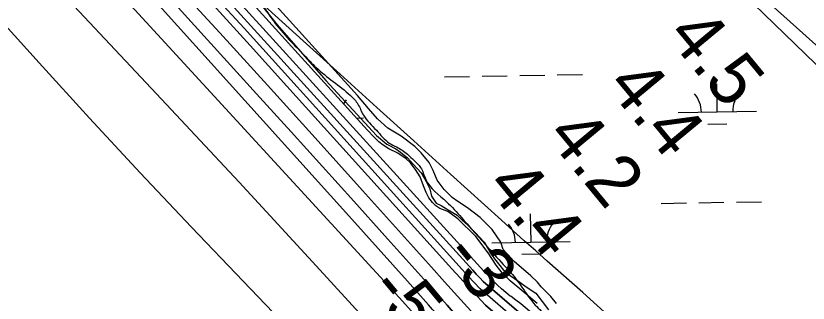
# Model space of a CAD drawing. Extents: x 3887375 to 3925618, y 296674 to 322633.
# Drawn here: x 3897913 to 3898925, y 310205 to 310572 of the extents above; entities that cross this region are included whole.
import ezdxf

# ---------------------------------------------------------------- set-up
doc = ezdxf.new("R2010")
doc.units = 0
for name, color, linetype in [('V-RIVR-EDGE', 7, 'Continuous'), ('V-RIVR-JETY', 7, 'Continuous'), ('V-RIVR-RANG', 7, 'Continuous'), ('V-TOPO-DPTH', 7, 'Continuous'), ('V-TOPO-MAJR', 7, 'Continuous'), ('V-TOPO-MINR', 7, 'Continuous'), ('V-TOPO-SHOR', 7, 'Continuous'), ('V-TOPO-WATR', 7, 'Continuous'), ('V-WETL-SWMP', 7, 'Continuous')]:
    doc.layers.add(name, color=color, linetype=linetype)

msp = doc.modelspace()

# ---------------------------------------------------------------- linework, layer by layer
at = {"layer": 'V-RIVR-EDGE'}
for points in [[(3896115.8, 312736.3), (3896123.6, 312723.7), (3896129.9, 312714.4), (3896135.6, 312703.7), (3896139.5, 312690.4), (3896139.8, 312681.4), (3896138.2, 312674.8), (3896136.8, 312674.1), (3896128.5, 312683.1), (3896119.6, 312696.5), (3896111.3, 312706.8), (3896107.3, 312707.8), (3896105, 312706.5), (3896104.3, 312701.1), (3896107.9, 312688.8), (3896111.2, 312681.2), (3896123.5, 312667.2), (3896140.7, 312647.2), (3896161, 312617.2), (3896188.5, 312584.9), (3896210, 312563.2), (3896237.6, 312538.5), (3896253.5, 312524.9), (3896271.4, 312512.5), (3896287.7, 312501.8), (3896299, 312494.8), (3896307, 312486.8), (3896325.8, 312456.2), (3896335.8, 312438.5), (3896350.7, 312424.2), (3896373.6, 312404.5), (3896404.8, 312381.8), (3896442, 312359.5), (3896468.9, 312343.4), (3896491.1, 312332.4), (3896500.1, 312327.1), (3896508.4, 312318.7), (3896515.3, 312306.4), (3896528.3, 312284.4), (3896534.9, 312271.8), (3896552.8, 312258.8), (3896583, 312239.7), (3896613.6, 312220), (3896639.8, 312198.7), (3896665.3, 312175.7), (3896698.5, 312153), (3896718.4, 312139), (3896747, 312114.6), (3896768.2, 312094.3), (3896793.7, 312068.3), (3896812.7, 312048.3), (3896828.9, 312030), (3896844.5, 312006.3), (3896867.4, 311982.3), (3896895.9, 311956), (3896949, 311910), (3896976.5, 311885.6), (3896985.2, 311878.6), (3896997.8, 311872.9), (3897005.4, 311870.2), (3897020, 311862.9), (3897041.6, 311845.9), (3897061.2, 311830.9), (3897070.1, 311823.9), (3897078.8, 311813.9), (3897087.7, 311797.5), (3897092.3, 311785.6), (3897097, 311776.9), (3897111.2, 311756.3), (3897119.5, 311747.3), (3897129.5, 311738.6), (3897149.4, 311722.6), (3897170.9, 311704.6), (3897186.2, 311690.6), (3897201.8, 311670.2), (3897228.6, 311633.3), (3897264.7, 311581.6), (3897280, 311565), (3897305.2, 311540), (3897328.4, 311515.6), (3897360.9, 311485.9), (3897388.8, 311458.3), (3897419.3, 311434.3), (3897433.9, 311420.3), (3897454.5, 311394.6), (3897475, 311368.3), (3897490.6, 311354.6), (3897505.6, 311336.6), (3897515.8, 311319.6), (3897527.8, 311305.3), (3897546.7, 311288.3), (3897564.6, 311280.6), (3897578.2, 311271.3), (3897592.8, 311257.9), (3897613.1, 311238.6), (3897630.3, 311218.9), (3897644.6, 311200.6), (3897648.9, 311196.6), (3897654.9, 311195.9), (3897664.8, 311187.9), (3897681.4, 311173.9), (3897696, 311156.2), (3897728.2, 311123.2), (3897747.7, 311099.3), (3897753.7, 311088.3), (3897756.7, 311085.6), (3897762.6, 311082.9), (3897779.6, 311067.6), (3897798.5, 311046.9), (3897815.4, 311028.6), (3897832, 311014.6), (3897852.2, 310999.9), (3897867.8, 310985.6), (3897880.8, 310970.2), (3897894, 310949.2), (3897907.6, 310928.6), (3897922.2, 310908.3), (3897948, 310879.6), (3897967.3, 310856.6), (3897987.8, 310835.3), (3898011.7, 310813.3), (3898048.6, 310785.3), (3898064.5, 310774.2), (3898081.4, 310759.2), (3898099.7, 310738.9), (3898112.9, 310724.6), (3898123.2, 310708.6), (3898130.8, 310696.3), (3898136.8, 310688.9), (3898147.4, 310677.3), (3898160, 310664.3), (3898168.9, 310655.3), (3898196.5, 310623.6), (3898206.1, 310609.3), (3898214, 310600.6), (3898230.3, 310582), (3898242.2, 310565.3), (3898262.4, 310541.3), (3898281.7, 310521.3), (3898296.6, 310506), (3898340.4, 310470.3), (3898350, 310459.3), (3898357, 310445.3), (3898373.6, 310426), (3898390.1, 310409.6), (3898399.4, 310404.6), (3898413.4, 310395.3), (3898421.7, 310387.3), (3898430, 310378.6), (3898436.6, 310363.3), (3898463.4, 310334.6), (3898482.3, 310314.6), (3898496.6, 310298.3), (3898513.2, 310279.7), (3898535.7, 310254.7), (3898547.3, 310242), (3898560.3, 310224.7), (3898576.5, 310203), (3898592.1, 310187.7), (3898611.3, 310166), (3898633.5, 310138.7), (3898638.2, 310134.4), (3898642.5, 310133), (3898652.1, 310127.7), (3898657.8, 310123.7), (3898665.4, 310115.7), (3898676.7, 310101.7), (3898686, 310090.7), (3898692.6, 310085.3), (3898699.2, 310080.3), (3898707.9, 310070), (3898714.5, 310056.4), (3898718.4, 310043.7), (3898720.4, 310041), (3898727.4, 310036.4), (3898760.3, 310015), (3898774.2, 310006), (3898785.5, 309994.3), (3898801.4, 309973.3), (3898808.7, 309959.4), (3898822.6, 309942.4), (3898837.9, 309924.7), (3898844.8, 309916.4), (3898858.7, 309899), (3898871.4, 309885.4), (3898894.5, 309850.4), (3898899.9, 309846.7), (3898908.5, 309840.7), (3898917.1, 309838), (3898920.4, 309835.7), (3898928.1, 309822.7), (3898935.4, 309812.7), (3898943.6, 309802.7), (3898951.9, 309787.7), (3898962.9, 309772.4), (3898972.5, 309757.4), (3898979.1, 309752.4), (3898987.1, 309749.1), (3898990.7, 309745.1), (3899002, 309727.8), (3899013.3, 309715.4), (3899031.2, 309696.4), (3899044.8, 309680.1), (3899055.7, 309665.5), (3899065, 309653.8), (3899074.6, 309640.1), (3899085.5, 309630.8), (3899093.8, 309628.1), (3899099.2, 309628.1), (3899103.2, 309626.1), (3899108.1, 309616.1), (3899114.7, 309606.4), (3899123.7, 309591.1), (3899128.3, 309582.8), (3899128.3, 309580.5), (3899127.6, 309569.2), (3899127.9, 309565.8), (3899132.9, 309561.5), (3899159.8, 309529.2), (3899191, 309497.2), (3899204.9, 309480.5), (3899212.2, 309470.2), (3899224.8, 309457.2), (3899244.7, 309437.5), (3899252.6, 309429.9), (3899261.9, 309422.9), (3899272.6, 309415.8), (3899279.5, 309406.5), (3899287.5, 309396.2), (3899300.1, 309376.5), (3899311.3, 309362.5), (3899327.9, 309343.2), (3899342.2, 309325.6), (3899360.1, 309304.6), (3899377.3, 309282.9), (3899414.5, 309240.6), (3899433.4, 309219.6), (3899447.3, 309203.9), (3899464.5, 309184.9), (3899479.1, 309166.9), (3899493.4, 309149.9)], [(3894498, 310522.4), (3894530, 310496.1), (3894553.8, 310474.7), (3894579.9, 310451.3), (3894614.8, 310419.2), (3894633.2, 310400.7), (3894662.8, 310372.4), (3894685.1, 310353.4), (3894692.4, 310347.1), (3894709.8, 310328.1), (3894746.6, 310285.3), (3894785.8, 310252.2), (3894809.6, 310225.9), (3894830.4, 310205.4), (3894852.7, 310189.9), (3894866.7, 310171.8), (3894915.2, 310120.3), (3894950.1, 310083.7), (3894971.4, 310062.8), (3894999, 310039.4), (3895025.2, 310017), (3895052.8, 309992.7), (3895093, 309952.3), (3895110.9, 309932.8), (3895141.4, 309903.1), (3895188.9, 309855.9), (3895222.8, 309821.3), (3895255.8, 309784.3), (3895319.2, 309722.5), (3895350.7, 309688.4), (3895358.4, 309676.3), (3895364.7, 309669.4), (3895374.9, 309663.1), (3895389, 309650.4), (3895410.8, 309628.1), (3895448.5, 309583.3), (3895480.5, 309554.1), (3895503.8, 309527.8), (3895533.8, 309499.5), (3895577.4, 309454.8), (3895606.9, 309425.5), (3895653.5, 309378.8), (3895685.9, 309349.1), (3895719.8, 309314.5), (3895749.4, 309285.8), (3895790.6, 309242.5), (3895837.1, 309195.8), (3895863.7, 309164.1), (3895900, 309127.6), (3895944.1, 309081.4), (3895955.7, 309070.7), (3895974.6, 309054.6), (3896002.3, 309033.1), (3896032.8, 309003.9), (3896062.8, 308972.3), (3896082.7, 308950.4), (3896119.5, 308911.9), (3896139.3, 308892.5), (3896152, 308889.5), (3896163.1, 308883.7), (3896167.9, 308873.9), (3896170.3, 308862.3), (3896184.4, 308844.3), (3896211, 308816), (3896224.1, 308810.2), (3896236.7, 308802.4), (3896249.8, 308786.8), (3896255.6, 308776.6), (3896270.6, 308766.4), (3896280.3, 308753.2), (3896295.8, 308737.2), (3896375.3, 308661.2), (3896425.2, 308610.1), (3896464.4, 308570.6), (3896519.6, 308515.6), (3896548.7, 308483), (3896563.2, 308467.5), (3896597.6, 308430.9), (3896635.9, 308396.4), (3896666.4, 308365.7), (3896681.4, 308349.6), (3896712.4, 308320.4), (3896746.3, 308287.3), (3896777.4, 308260), (3896801.6, 308235.7), (3896820.5, 308215.3), (3896842.8, 308195.3), (3896851.5, 308181.2), (3896882.5, 308148.6), (3896918.8, 308116.4), (3896962.9, 308074.6), (3896997.8, 308033.2), (3897029.2, 307998.6), (3897042.3, 307985), (3897083.5, 307945.6), (3897107.2, 307918.3), (3897123.2, 307898.8), (3897130, 307898.8), (3897142.1, 307893), (3897146, 307882.3), (3897149.9, 307874), (3897162.9, 307860.4), (3897188.6, 307833.1), (3897229.3, 307788.8), (3897267.6, 307752.3), (3897300.5, 307715.8), (3897334.4, 307680.3), (3897361.5, 307651.1), (3897384.8, 307628.2), (3897411.4, 307599), (3897445.8, 307563.4), (3897494.3, 307516.7), (3897543.2, 307462.7), (3897584.8, 307418.4), (3897609, 307394), (3897646.8, 307355.6), (3897678.8, 307323.9), (3897715.1, 307290.3), (3897752, 307253.3), (3897767, 307236.3), (3897837.7, 307158.4), (3897886.6, 307104.4), (3897936, 307048.4), (3897965.5, 307015.3), (3898010.6, 306970.1), (3898027.5, 306949.1), (3898045, 306936), (3898063.9, 306914.1), (3898089, 306882.5), (3898117.1, 306854.7), (3898160.2, 306801.2), (3898195.6, 306763.7), (3898235.8, 306719.9), (3898261.5, 306693.6), (3898297.3, 306650.8), (3898332.7, 306612.3), (3898369.9, 306568), (3898397.5, 306534.9), (3898422.2, 306505.8), (3898462.9, 306455.1), (3898495.3, 306417.2), (3898522, 306382.2), (3898601.4, 306284.3), (3898652.2, 306228.4), (3898693.4, 306177.3), (3898729.7, 306130.6), (3898777.1, 306074.1), (3898825.5, 306014.3), (3898848.8, 305986), (3898904, 305917.4), (3898957.2, 305854.7), (3898984.4, 305818.2), (3899049.7, 305744.7), (3899107.8, 305679.4), (3899129.1, 305651.7), (3899142.7, 305630.3), (3899156.2, 305611.8), (3899175.1, 305588), (3899224, 305529.6), (3899256, 305493.6), (3899288.9, 305449.3), (3899312.6, 305415.2), (3899375.6, 305336.9), (3899410.9, 305296), (3899442.8, 305252.2), (3899470.4, 305211.9), (3899531.4, 305133.5), (3899579.3, 305071.2), (3899616.1, 305026), (3899647.1, 304986.1), (3899690.7, 304931.1), (3899729.4, 304876.6), (3899753.6, 304846.9), (3899770.6, 304821.6), (3899817.5, 304755.5), (3899845.6, 304713.2), (3899868.3, 304677.2), (3899889.6, 304650.4), (3899911.4, 304623.6), (3899955.4, 304569.1), (3899987.4, 304526.8), (3900012.6, 304494.2), (3900025.6, 304476.2), (3900037.2, 304456.8), (3900061.9, 304431.9), (3900070.7, 304424.1), (3900074.5, 304414.4), (3900075, 304404.2), (3900073, 304397.9), (3900071.5, 304388.7), (3900071.5, 304383.8), (3900075.9, 304379), (3900087.1, 304374.1), (3900096.3, 304367.7), (3900108.4, 304362.4), (3900117.1, 304353.6), (3900140.8, 304326.3), (3900165.5, 304299.1), (3900226.1, 304227.6), (3900277.9, 304164.3), (3900320, 304105.9), (3900352.4, 304062.6), (3900384.4, 304023.2), (3900411.5, 303988.2), (3900438.1, 303954.1), (3900462.8, 303926.8), (3900556.2, 303812.5), (3900597.9, 303762.9), (3900633.7, 303716.6), (3900652.6, 303691.3), (3900702, 303626.6), (3900774.6, 303530.8), (3900849.1, 303437.3), (3900903.4, 303371.2), (3900928.1, 303343.4), (3900948.9, 303317.6), (3901001.2, 303258.3), (3901038.9, 303216.9), (3901074.8, 303173.1), (3901092.2, 303147.3), (3901171.6, 303050.5), (3901205, 303008.6), (3901238.4, 302968.2), (3901274.7, 302927.8), (3901303.3, 302893.8), (3901344, 302847.5), (3901366.7, 302816.4), (3901404.5, 302770.2), (3901454.4, 302715.2), (3901507.2, 302659.2), (3901551.7, 302608.1), (3901584.7, 302570.6), (3901650, 302491.3), (3901681, 302443.6), (3901717.8, 302388.2), (3901785.5, 302298.2), (3901789.5, 302293.3)]]:
    msp.add_spline(points, degree=3, dxfattribs=at)
at = {"layer": 'V-RIVR-JETY'}
for points in [[(3898214.4, 310601.2), (3898246.9, 310560.5), (3898308.9, 310489.4), (3898373.9, 310419.3), (3898387.1, 310408.1), (3898398.3, 310402), (3898404.4, 310397.9), (3898413.5, 310390.8), (3898420.7, 310382.7), (3898430.8, 310371.5), (3898436.9, 310361.3), (3898442, 310351.2), (3898444, 310342), (3898450.1, 310332.9), (3898456.2, 310329.8), (3898463.3, 310325.8), (3898476.6, 310317.6), (3898482.7, 310311.5), (3898490.8, 310304.4), (3898499.9, 310295.3), (3898511.1, 310283.1), (3898518.2, 310271.9), (3898524.3, 310261.8), (3898529.4, 310255.7), (3898537.5, 310245.5), (3898556.8, 310232.3), (3898565, 310226.2), (3898577.2, 310218.1), (3898593.4, 310196.7)], [(3898603.6, 310204.8), (3898596.5, 310214), (3898584.3, 310226.2), (3898579.2, 310232.3), (3898571.1, 310240.4), (3898549.7, 310258.7), (3898535.5, 310273.9), (3898532.4, 310283.1), (3898521.3, 310299.4), (3898506, 310314.6), (3898489.8, 310326.8), (3898477.6, 310334.9), (3898470.5, 310340), (3898460.3, 310350.2), (3898451.1, 310362.4), (3898446.1, 310374.6), (3898441, 310384.7), (3898430.8, 310396.9), (3898422.7, 310405), (3898405.4, 310418.3), (3898388.1, 310428.4), (3898374.9, 310440.6), (3898363.7, 310453.8), (3898349.5, 310470.1), (3898241.8, 310589)]]:
    msp.add_lwpolyline(points, dxfattribs=at)
at = {"layer": 'V-TOPO-DPTH'}
for points in [[(3898945.1, 309652), (3898919.2, 309682.5), (3898893.2, 309712.8), (3898867.3, 309743.1), (3898842.5, 309772), (3898803.9, 309816.6), (3898765.3, 309861.1), (3898726.5, 309905.5), (3898687.6, 309949.8), (3898485.5, 310178.5), (3898474.7, 310190.7), (3898463.9, 310202.9), (3898453, 310215.1), (3898442.1, 310227.3), (3898384.5, 310291.4), (3898344.7, 310335.6), (3898304.9, 310379.8), (3898265, 310423.8), (3898225, 310467.8), (3897965.8, 310752.8)], [(3897965.8, 310752.8), (3898225, 310467.8), (3898265, 310423.8), (3898304.9, 310379.8), (3898344.7, 310335.6), (3898384.5, 310291.4), (3898442.1, 310227.3), (3898453, 310215.1), (3898463.9, 310202.9), (3898474.7, 310190.7), (3898485.5, 310178.5), (3898687.6, 309949.8), (3898726.5, 309905.5), (3898765.3, 309861.1), (3898803.9, 309816.6), (3898842.5, 309772), (3898867.3, 309743.1), (3898893.2, 309712.8), (3898919.2, 309682.5), (3898945.1, 309652)], [(3899686.2, 308933.2), (3899549.1, 309098.8), (3899533, 309118.6), (3899517.2, 309138.6), (3899501.6, 309159), (3899486.4, 309179.5), (3899361.7, 309350.3), (3899308.5, 309422.5), (3899255, 309494.5), (3899200.9, 309566), (3899146.4, 309637.2), (3899056.5, 309753.8), (3899046.5, 309766.3), (3899036.2, 309778.6), (3899025.5, 309790.5), (3898510.2, 310233), (3898505.7, 310237.7), (3898501.2, 310242.5), (3898496.8, 310247.3), (3898150, 310629.3)], [(3898150, 310629.3), (3898496.8, 310247.3), (3898501.2, 310242.5), (3898505.7, 310237.7), (3898510.2, 310233), (3899025.5, 309790.5), (3899036.2, 309778.6), (3899046.5, 309766.3), (3899056.5, 309753.8), (3899146.4, 309637.2), (3899200.9, 309566), (3899255, 309494.5), (3899308.5, 309422.5), (3899361.7, 309350.3), (3899486.4, 309179.5), (3899501.6, 309159), (3899517.2, 309138.6), (3899533, 309118.6), (3899549.1, 309098.8), (3899686.2, 308933.2)], [(3898936, 309711.3), (3898901.5, 309748.8), (3898880.4, 309771.8), (3898859.2, 309794.9), (3898838.1, 309818), (3898817, 309841.1), (3898494.1, 310195.7), (3898477.4, 310214.2), (3898460.7, 310232.7), (3898444, 310251.2), (3898356.1, 310348.9), (3898295.4, 310416.1), (3898234.6, 310483.3), (3898173.6, 310550.2), (3898112.4, 310617.1)], [(3898112.4, 310617.1), (3898173.6, 310550.2), (3898234.6, 310483.3), (3898295.4, 310416.1), (3898356.1, 310348.9), (3898444, 310251.2), (3898460.7, 310232.7), (3898477.4, 310214.2), (3898494.1, 310195.7), (3898817, 309841.1), (3898838.1, 309818), (3898859.2, 309794.9), (3898880.4, 309771.8), (3898901.5, 309748.8), (3898936, 309711.3)], [(3899016.7, 309835.9), (3898780.7, 310081.6), (3898745.8, 310117), (3898710.3, 310151.8), (3898674, 310185.8), (3898637.1, 310219.1), (3898591.8, 310259), (3898577.1, 310272), (3898562.5, 310285), (3898547.9, 310298.1), (3898533.4, 310311.2), (3898468.4, 310370), (3898421.4, 310412.5), (3898374.4, 310455), (3898327.3, 310497.4), (3898280.2, 310539.9), (3898226.5, 310588.3)], [(3898165.3, 310585.9), (3898212.4, 310534.2), (3898259.4, 310482.3), (3898470, 310249.3), (3898480.7, 310237.5), (3898491.4, 310225.9), (3898502.3, 310214.3), (3898513.2, 310202.8), (3898975.1, 309805.6)], [(3898165.3, 310585.9), (3898212.4, 310534.2), (3898259.4, 310482.3), (3898470, 310249.3), (3898480.7, 310237.5), (3898491.4, 310225.9), (3898502.3, 310214.3), (3898513.2, 310202.8), (3898975.1, 309805.6)]]:
    msp.add_lwpolyline(points, dxfattribs=at)
at = {"layer": 'V-TOPO-MAJR'}
msp.add_lwpolyline([(3898936, 309624.8), (3898918.2, 309645.9), (3898900.3, 309666.9), (3898882.4, 309688), (3898864.5, 309709.1), (3898648.6, 309963.4), (3898615.9, 310001.7), (3898583, 310040), (3898550, 310078.1), (3898516.9, 310116), (3898460.6, 310180.3), (3898455.6, 310186.1), (3898450.5, 310191.8), (3898445.4, 310197.5), (3898440.3, 310203.2), (3898413.2, 310233.5), (3898394.5, 310254.3), (3898375.8, 310275.1), (3898357.1, 310295.9), (3898338.4, 310316.6), (3897943.8, 310754.4)], dxfattribs=at)
at = {"layer": 'V-TOPO-MINR'}
for points in [[(3898945.1, 309652), (3898919.2, 309682.5), (3898893.2, 309712.8), (3898867.3, 309743.1), (3898842.5, 309772), (3898803.9, 309816.6), (3898765.3, 309861.1), (3898726.5, 309905.5), (3898687.6, 309949.8), (3898485.5, 310178.5), (3898474.7, 310190.7), (3898463.9, 310202.9), (3898453, 310215.1), (3898442.1, 310227.3), (3898384.5, 310291.4), (3898344.7, 310335.6), (3898304.9, 310379.8), (3898265, 310423.8), (3898225, 310467.8), (3897965.8, 310752.8)], [(3899015.4, 309818.8), (3898558.3, 310204.4), (3898551.9, 310209), (3898545.6, 310213.7), (3898544.6, 310214.4), (3898539, 310218.9), (3898533.5, 310223.5), (3898528.2, 310228.4), (3898523.1, 310233.5), (3898515.4, 310241.4), (3898513.1, 310243.8), (3898510.8, 310246.3), (3898095.6, 310702.3)], [(3898365.9, 310177.8), (3898296.9, 310252.8), (3898247.6, 310306.2), (3898198.2, 310359.5), (3898148.6, 310412.7), (3898099, 310465.7), (3897888.5, 310689.8)], [(3899686.2, 308933.2), (3899549.1, 309098.8), (3899533, 309118.6), (3899517.2, 309138.6), (3899501.6, 309159), (3899486.4, 309179.5), (3899361.7, 309350.3), (3899308.5, 309422.5), (3899255, 309494.5), (3899200.9, 309566), (3899146.4, 309637.2), (3899056.5, 309753.8), (3899046.5, 309766.3), (3899036.2, 309778.6), (3899025.5, 309790.5), (3898510.2, 310233), (3898505.7, 310237.7), (3898501.2, 310242.5), (3898496.8, 310247.3), (3898150, 310629.3)], [(3899238.1, 309092), (3898819.1, 309565.3), (3898810.1, 309575.4), (3898801.2, 309585.5), (3898792.2, 309595.6), (3898783.3, 309605.7), (3898673.1, 309729.8), (3898617.7, 309791.7), (3898562, 309853.3), (3898505.8, 309914.3), (3898449.2, 309975.1), (3898380.5, 310048.3), (3898358, 310072.2), (3898335.4, 310096), (3898312.7, 310119.8), (3898289.9, 310143.5), (3898203.3, 310233.4), (3898137.5, 310302.3), (3898072.1, 310371.6), (3898007.4, 310441.5), (3897943.1, 310511.8), (3897848, 310616.9)], [(3898936, 309711.3), (3898901.5, 309748.8), (3898880.4, 309771.8), (3898859.2, 309794.9), (3898838.1, 309818), (3898817, 309841.1), (3898494.1, 310195.7), (3898477.4, 310214.2), (3898460.7, 310232.7), (3898444, 310251.2), (3898356.1, 310348.9), (3898295.4, 310416.1), (3898234.6, 310483.3), (3898173.6, 310550.2), (3898112.4, 310617.1)], [(3898926, 309598.1), (3898903.6, 309624.6), (3898881.1, 309651.2), (3898858.7, 309677.8), (3898836.2, 309704.3), (3898525, 310072.7), (3898510, 310090.4), (3898494.9, 310108), (3898479.8, 310125.6), (3898464.6, 310143.1), (3898449.3, 310160.6), (3898433.9, 310178), (3898418.3, 310195.2), (3898402.7, 310212.4), (3898050.8, 310595.8)], [(3899818.9, 308745.4), (3899546.6, 309073.5), (3899524.8, 309100.4), (3899503.3, 309127.5), (3899482.4, 309155), (3899461.8, 309182.9), (3899222.5, 309512.5), (3899190.6, 309556.1), (3899158.5, 309599.5), (3899126, 309642.7), (3899093.2, 309685.7), (3899039.4, 309755.7), (3899033.3, 309763.4), (3899026.9, 309771), (3899020.4, 309778.3), (3898506.2, 310223.5), (3898498.5, 310231.7), (3898490.8, 310240), (3898483.3, 310248.3), (3898204.6, 310556), (3898167.8, 310596.5)], [(3898975.1, 309805.6), (3898513.2, 310202.8), (3898502.3, 310214.3), (3898491.4, 310225.9), (3898480.7, 310237.5), (3898470, 310249.3), (3898259.4, 310482.3), (3898212.4, 310534.2), (3898165.3, 310585.9)]]:
    msp.add_lwpolyline(points, dxfattribs=at)
at = {"layer": 'V-TOPO-SHOR'}
for points in [[(3897935.1, 311546.8), (3897957.3, 311509.8), (3898216, 311204.8), (3898572.4, 310859.4), (3898938.8, 310531.4), (3898958.5, 310508.5), (3899351.9, 310099), (3899641, 309811.7), (3899765.1, 309671.9), (3899810.6, 309602.6), (3899841.8, 309549.5), (3899864.3, 309508.2), (3899943.9, 309405.8)], [(3899387, 309454.8), (3899419.8, 309471.2), (3899445, 309477.4), (3899465.5, 309474.2), (3899492.1, 309469.6), (3899517.1, 309472.9), (3899551.9, 309488.1), (3899586.9, 309521.3), (3899610.4, 309531.9), (3899663, 309542.2), (3899700.2, 309560.8), (3899721.1, 309578.6), (3899729.9, 309606.7), (3899732.8, 309648.9), (3899729.4, 309676.7), (3899703.2, 309715.5), (3899662.7, 309753), (3899544.2, 309878.9), (3899371.2, 310053), (3899236.2, 310204.4), (3899159, 310275.9), (3899094.8, 310349), (3898934.6, 310510.7), (3898790.3, 310650.6)]]:
    msp.add_lwpolyline(points, dxfattribs=at)
at = {"layer": 'V-TOPO-WATR'}
msp.add_lwpolyline([(3899016.7, 309835.9), (3898780.7, 310081.6), (3898745.8, 310117), (3898710.3, 310151.8), (3898674, 310185.8), (3898637.1, 310219.1), (3898591.8, 310259), (3898577.1, 310272), (3898562.5, 310285), (3898547.9, 310298.1), (3898533.4, 310311.2), (3898468.4, 310370), (3898421.4, 310412.5), (3898374.4, 310455), (3898327.3, 310497.4), (3898280.2, 310539.9), (3898226.5, 310588.3)], dxfattribs=at)
at = {"layer": 'V-WETL-SWMP'}
for p, q in [((3898604.7, 310496.6), (3898636.7, 310497.1)), ((3898460.7, 310494.1), (3898492.7, 310494.6)), ((3898508.7, 310494.9), (3898540.7, 310495.5)), ((3898556.7, 310495.7), (3898588.7, 310496.3)), ((3898808.9, 310449.3), (3898808.3, 310485.3)), ((3898758.9, 310448.5), (3898858.9, 310450.2)), ((3898348.2, 310441.4), (3898357, 310441.6)), ((3898797.1, 310433.7), (3898821.1, 310434.1)), ((3898737.5, 310332.6), (3898769.5, 310333.2)), ((3898785.5, 310333.5), (3898817.5, 310334)), ((3898833.5, 310334.3), (3898865.4, 310334.8)), ((3898571.2, 310283.3), (3898570.6, 310319.3)), ((3898521.2, 310282.5), (3898621.2, 310284.2)), ((3898559.5, 310267.7), (3898583.5, 310268.1))]:
    msp.add_line(p, q, dxfattribs=at)
for points in [[(3899943.9, 309405.8), (3899864.3, 309508.2), (3899841.8, 309549.5), (3899810.6, 309602.6), (3899765.1, 309671.9), (3899641, 309811.7), (3899351.9, 310099), (3898958.5, 310508.5), (3898938.8, 310531.4), (3898572.4, 310859.4), (3898216, 311204.8), (3897957.3, 311509.8), (3897935.1, 311546.8)], [(3898790.3, 310650.6), (3898934.6, 310510.7)], [(3898449.7, 310329.4), (3898445.3, 310333.9), (3898440.6, 310339.8), (3898437.4, 310346.5), (3898433.9, 310354.9), (3898429.4, 310366.3), (3898423.8, 310375.7), (3898416.7, 310384.6), (3898411.6, 310389.6), (3898401.2, 310396.6), (3898389.7, 310402.2), (3898382.1, 310407), (3898376.6, 310411.3), (3898370.3, 310417.4), (3898362.2, 310426), (3898265.1, 310532.6), (3898207.8, 310596.5)], [(3898579, 310205.1), (3898559.6, 310221.4), (3898544.4, 310233.9), (3898534.4, 310243.9), (3898526.6, 310253.9), (3898516.6, 310269.4), (3898500.6, 310290.6), (3898477.7, 310313.1), (3898464.8, 310322.2), (3898454.7, 310326.2), (3898449.7, 310329.4)]]:
    msp.add_lwpolyline(points, dxfattribs=at)
for centre, start, end in [((3898753.6, 310448.8), 0.2115, 41.7552), ((3898864.1, 310450.7), 140.2115, 181.7552), ((3898362.3, 310442.1), 140.2115, 150.2765), ((3898516, 310282.9), 0.2115, 41.7552), ((3898626.4, 310284.8), 140.2115, 181.7552)]:
    msp.add_arc(centre, 35.2, start, end, dxfattribs=at)

# ---------------------------------------------------------------- texts
at = {"layer": 'V-RIVR-RANG'}
for s, rotation, p in [('4.5', 309.6083, (3898742.9, 310546.3)), ('4.4', 309.6083, (3898666, 310482.3)), ('4.2', 309.6083, (3898589.1, 310418.4)), ('4.4', 309.6083, (3898512.2, 310354.4)), ('-3', 309.6083, (3898456.4, 310265.1)), ('-59', 309.8958, (3898361.6, 310222.1))]:
    msp.add_text(s, height=67, rotation=rotation, dxfattribs=at).set_placement(p)

doc.saveas('drawing.dxf')
